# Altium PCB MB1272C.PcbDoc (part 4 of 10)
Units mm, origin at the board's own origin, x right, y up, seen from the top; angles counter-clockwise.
Board outline 101 x 71 mm, 6 copper layers (Top Layer, Signal Layer 1, Signal Layer 2, Signal Layer 3, Signal Layer 4, Bottom Layer), stack 1.552 mm thick; 520 components, 478 nets, 2156 pads, 1894 vias.
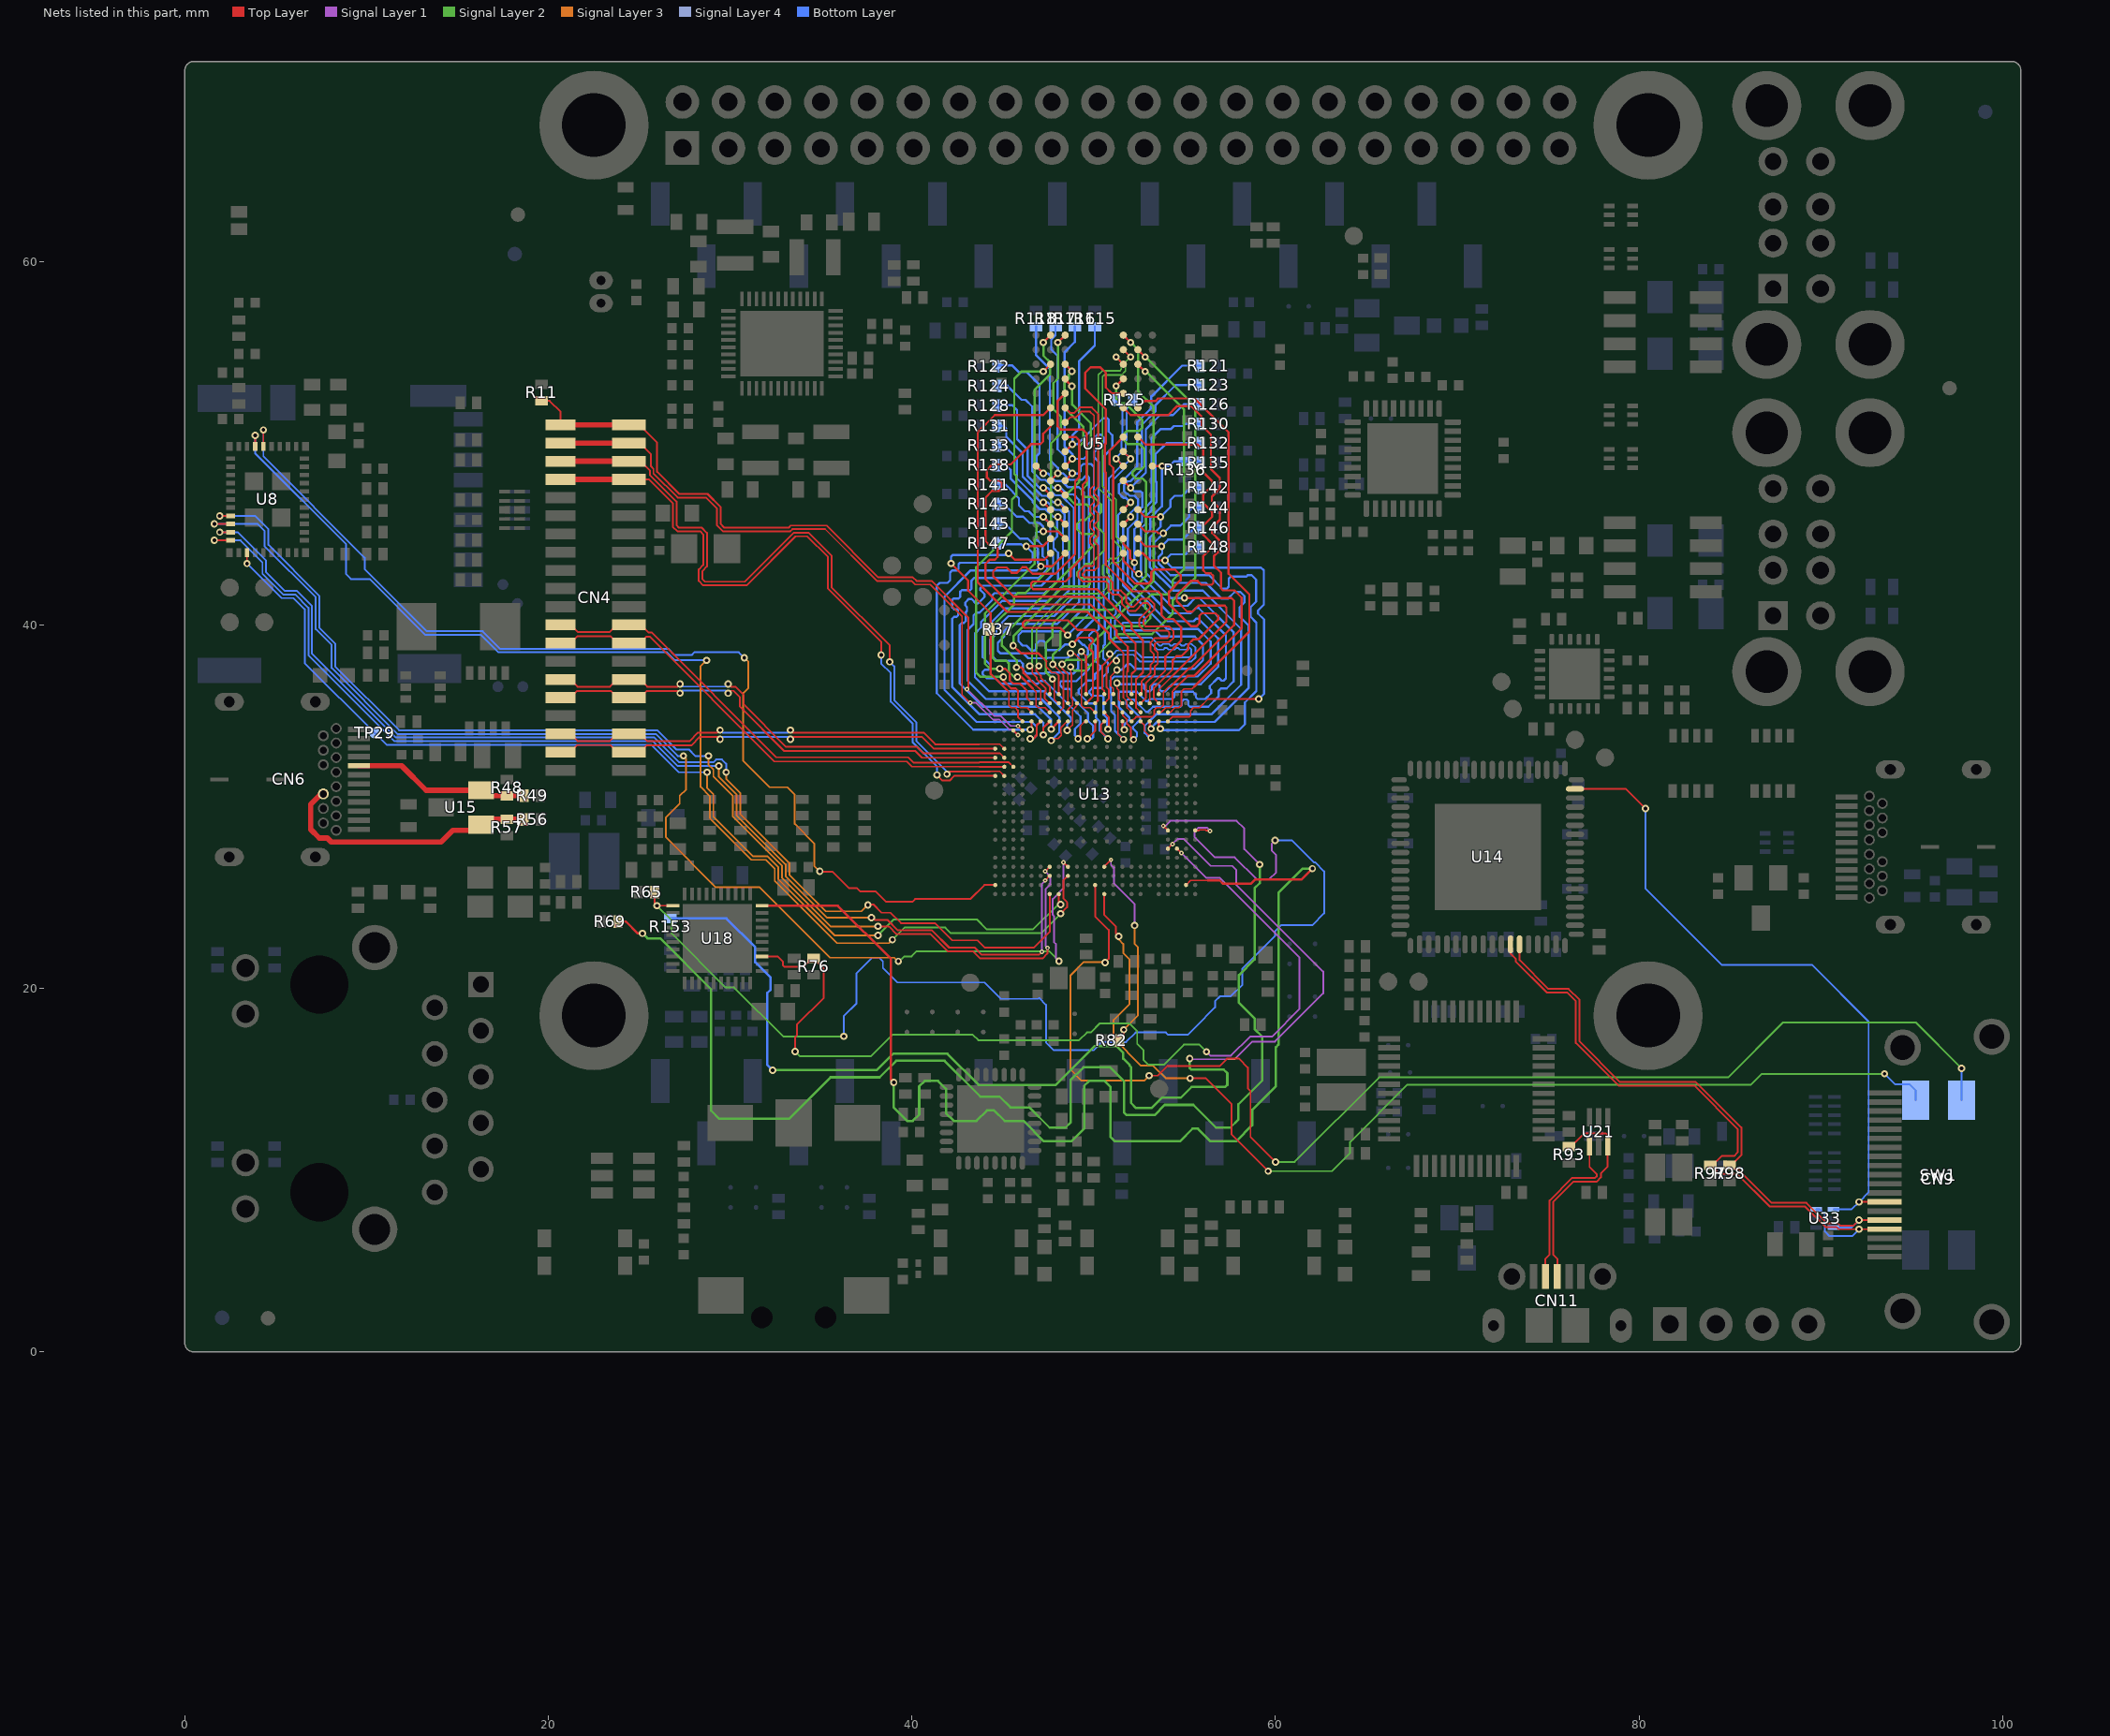
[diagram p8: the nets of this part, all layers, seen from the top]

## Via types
v1: diameter 0.4, hole 0.2, Top Layer to Bottom Layer, tented both sides, 912 vias
v2: diameter 0.25, hole 0.1, Top Layer to Signal Layer 1, tented top, 493 vias
v3: diameter 0.6, hole 0.3, Top Layer to Bottom Layer, tented both sides, 452 vias
v4: diameter 0.25, hole 0.1, Top Layer to Signal Layer 1, tented both sides, 37 vias

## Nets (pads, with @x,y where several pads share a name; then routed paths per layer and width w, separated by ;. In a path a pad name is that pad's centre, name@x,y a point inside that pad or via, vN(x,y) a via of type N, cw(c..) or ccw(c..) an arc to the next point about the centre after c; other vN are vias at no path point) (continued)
BOOT0: SW1.1 U13.N1 | length 60.5
  Top Layer w0.1: U13.N1@50.58,25.19 50.58,24.034 51.23,23.384 51.23,23.015 v1(51.38,22.865) ; v1(55.3,15.05) 56.175,15.05 57.575,13.65 57.575,11.97 v1(59.6,9.945)
  Signal Layer 2 w0.1: v1(59.6,9.945) 63.095,9.945 64.1,10.95 64.1,11.55 67.25,14.7 86.15,14.7 86.75,15.3 v1(93.5,15.3)
  Signal Layer 3 w0.1: v1(51.38,22.865) 51.38,22.694 51.625,22.449 51.625,21.95 51.975,21.6 51.975,19.15 51.1,18.275 51.1,17.25 52.6,15.75 53.278,15.75 53.978,15.05 v1(55.3,15.05)
  Bottom Layer w0.1: v1(93.5,15.3) 94.075,14.725 94.875,14.725 95.205,14.395 SW1.1@95.205,13.85
BOOT1: R82.2 U13.N4 | length 11.5
  Top Layer w0.1: U13.N4@50.575,26.695 U13.N4@50.58,26.69 50.58,26.705 v2(50.95,27.075) ; R82.2@51.425,17.125 51.65,17.35 v1(51.65,17.725)
  Signal Layer 1 w0.1: v2(50.95,27.075) 50.95,26.8 51.105,26.645 51.105,25.787 52.255,24.636 v1(52.255,23.465)
  Signal Layer 3 w0.1: v1(51.65,17.725) 52.425,18.5 52.425,22.275 52.255,22.445 v1(52.255,23.465)
BOOT2: SW1.2 U13.M2 | length 72.3
  Top Layer w0.1: U13.M2@50.08,25.69 50.08,23.968 50.83,23.218 50.83,21.63 v1(50.625,21.425) ; v1(53.05,15.2) 53.525,15.2 54.05,15.725 56.926,15.725 57.331,16.129 57.996,16.129 58.475,15.65 58.475,14.495 58.625,14.345 58.625,11.825 v1(60,10.45)
  Signal Layer 2 w0.1: v1(60,10.45) 61.05,10.45 65.7,15.1 84.9,15.1 87.925,18.125 95.215,18.125 v1(97.745,15.595)
  Signal Layer 3 w0.1: v1(50.625,21.425) 50.625,21.45 49.45,21.45 48.725,20.725 48.725,15.525 49.325,14.925 52.775,14.925 v1(53.05,15.2)
  Bottom Layer w0.1: SW1.2@97.745,13.85 v1(97.745,15.595)
BT_DEV_WAKE: U8.39 U13.J3 | length 67
  Top Layer w0.09: 48.53,24.715 48.53,24.753 48.33,24.953 48.33,25.94 U13.J3@48.58,26.19
  Top Layer w0.1: U8.39@3.875,49.825 v1(3.875,50.425) ; v1(48.18,24.115) 48.53,24.465 48.53,24.715
  Signal Layer 2 w0.1: v1(38.925,22.675) 39.6,23.35 41.84,23.35 42.15,23.04 47.105,23.04 v1(48.18,24.115)
  Signal Layer 3 w0.1: v1(28.7,38.05) 28.38,37.73 28.38,31.09 28.88,30.59 28.88,29.356 31.161,27.075 31.953,27.075 32.455,26.573 32.455,25.917 35.882,22.49 38.74,22.49 v1(38.925,22.675)
  Bottom Layer w0.1: v1(3.875,50.425) 3.875,49.44 8.875,44.44 8.875,42.789 9.139,42.525 10.167,42.525 13.242,39.45 16.3,39.45 17.26,38.49 26.519,38.49 26.959,38.05 v1(28.7,38.05)
BT_HOST_WAKE: U8.38 U13.A2 | length 58.9
  Top Layer w0.1: U8.38@4.325,49.825 v1(4.325,50.726) ; v1(34.93,26.44) 34.955,26.415 35.644,26.415 36.554,25.506 36.98,25.506 37.144,25.341 38.004,25.341 38.58,24.765 40.03,24.765 40.18,24.915 43.208,24.915 43.983,25.69 U13.A2@44.58,25.69
  Signal Layer 3 w0.1: v1(30.78,38.19) 31.004,37.966 31.004,36.531 30.725,36.252 30.725,32.509 32.168,31.066 33.148,31.066 33.55,30.664 33.55,29.049 34.63,27.969 34.63,26.74 v1(34.93,26.44)
  Bottom Layer w0.1: v1(4.325,50.726) 4.325,49.272 9.901,43.697 9.901,43.074 13.325,39.65 16.383,39.65 17.343,38.69 26.601,38.69 26.951,38.34 27.882,38.34 28.032,38.49 30.48,38.49 v1(30.78,38.19)
BT_PCM_CLK: U8.11 U13.G3 | length 63.7
  Top Layer w0.1: v1(1.624,44.65) U8.11@2.525,44.65 ; v1(37.78,23.89) v1@37.78,23.94 ; v1@37.78,23.94 37.955,23.765 38.661,23.765 39.237,23.19 41.104,23.19 42.049,22.245 43.442,22.245 43.837,21.85 46.99,21.85 v4(47.15,22.01) ; v2(47.33,25.94) U13.G3@47.58,26.19
  Signal Layer 1 w0.1: v4(47.15,22.01) 47.15,25.76 v2(47.33,25.94)
  Signal Layer 3 w0.1: v1(29.38,32.24) 29.38,31.639 30.35,30.669 30.35,29.526 33.055,26.821 33.055,26.165 35.33,23.89 v1(37.78,23.89)
  Bottom Layer w0.1: v1(1.624,44.65) 3.067,44.65 4.275,43.442 4.275,42.806 5.406,41.675 6.069,41.675 6.8,40.944 6.8,38.336 11.536,33.6 25.745,33.6 27.105,32.24 28.805,32.24 v1(29.38,32.24)
BT_PCM_SDI: U8.10 U13.G1 | length 62
  Top Layer w0.1: v1(1.925,45.1) U8.10@2.525,45.1 ; v1(37.58,24.59) 37.605,24.615 37.882,24.615 38.332,24.165 38.827,24.165 39.402,23.59 41.269,23.59 42.214,22.645 43.608,22.645 44.003,22.25 46.713,22.25 47.58,23.117 U13.G1@47.58,25.19
  Signal Layer 3 w0.1: v1(29.78,31.89) 29.78,31.522 30.55,30.752 30.55,29.609 33.255,26.904 33.255,26.248 35.263,24.24 37.225,24.24 37.575,24.59 v1(37.58,24.59)
  Bottom Layer w0.1: v1(1.925,45.1) 2.9,45.1 4.475,43.525 4.475,42.889 5.489,41.875 6.152,41.875 7,41.027 7,38.419 11.619,33.8 25.828,33.8 27.188,32.44 29.08,32.44 29.23,32.59 29.555,32.59 29.78,32.365 v1(29.78,31.89)
BT_PCM_SDO: U8.9 U13.J4 | length 70.5
  Top Layer w0.1: v1(1.624,45.55) U8.9@2.525,45.55 ; v2(48.33,26.94) U13.J4@48.58,26.69
  Signal Layer 1 w0.1: v1(48.09,21.5) 47.92,21.67 47.92,21.867 47.925,21.872 47.925,22.427 47.816,22.536 47.816,23.984 47.75,24.05 47.75,24.92 48.33,25.5 v2(48.33,26.94)
  Signal Layer 2 w0.1: v1(39.255,21.49) 39.255,21.44 39.579,21.765 39.98,21.765 40.255,22.04 47.55,22.04 v1(48.09,21.5)
  Signal Layer 3 w0.1: v1(27.429,32.79) 27.58,32.64 27.58,30.949 27.225,30.594 27.225,30.16 26.475,29.41 26.475,28.311 29.221,25.565 31.624,25.565 35.499,21.69 39.03,21.69 39.23,21.49 v1(39.255,21.49)
  Signal Layer 4 w0.1: v1(27.429,32.79) v1@27.48,32.74
  Bottom Layer w0.1: v1(1.624,45.55) 4.017,45.55 4.4,45.167 4.4,44.317 7.2,41.517 7.2,39.761 8.075,38.886 8.075,38.513 ; 8.074,38.512 8.074,37.628 11.702,34 25.911,34 27.12,32.79 v1(27.429,32.79)
BT_PCM_WS: U8.8 U13.G4 | length 65.3
  Top Layer w0.1: v1(1.925,46) U8.8@2.525,46 ; v1(38.13,23.415) 38.729,23.414 39.154,22.99 41.021,22.99 41.966,22.045 43.359,22.045 43.754,21.65 47.179,21.65 47.45,21.921 v4(47.45,22.23) ; v2(47.33,26.44) U13.G4@47.58,26.69
  Signal Layer 1 w0.1: v2(47.33,26.44) 47.605,26.165 47.605,25.715 47.35,25.46 47.35,22.33 v4(47.45,22.23)
  Signal Layer 3 w0.1: v1(28.805,32.79) 28.805,32.315 29.08,32.04 29.08,31.656 30.15,30.586 30.15,29.444 32.855,26.739 32.855,26.082 35.522,23.415 v1(38.13,23.415)
  Bottom Layer w0.1: v1(1.925,46) 3.85,46 4.6,45.25 4.6,44.4 7.4,41.6 7.4,39.844 8.275,38.969 8.275,37.886 8.274,37.711 11.785,34.2 25.994,34.2 27.053,33.14 27.73,33.14 28.08,32.79 v1(28.805,32.79)
BT_REG_ON: TP29.1 U8.14 U13.H1 | length 59.1
  Top Layer w0.1: v1(3.425,43.375) U8.14@3.425,43.975 ; U13.H1@48.08,25.19 48.08,24.64 48.105,24.615 v1(48.18,24.615)
  Signal Layer 2 w0.1: v1(38.13,22.915) 39.005,23.79 43.58,23.79 44.13,23.24 44.81,23.24 46.655,23.24 48.105,24.69 v1(48.18,24.615)
  Signal Layer 3 w0.1: v1(28.73,31.89) 28.73,31.04 29.08,30.69 29.08,29.439 31.244,27.275 32.036,27.275 32.655,26.656 32.655,25.999 35.74,22.915 v1(38.13,22.915)
  Bottom Layer w0.1: v1(3.425,43.375) 3.425,43.373 5.323,41.475 5.986,41.475 6.6,40.861 6.6,37.9 TP29.1@10.45,34.05 11.1,33.4 25.662,33.4 27.172,31.89 v1(28.73,31.89)
CC1: CN6.A5 R48.2 R49.1 U15.2 | length 9.8
  Top Layer w0.3: CN6.A5@9.58,32.25 11.925,32.25 13.275,30.9 U15.2@16.3,30.9 16.6,30.6 R48.2@17.725,30.6 R49.1@18.65,30.6
CC2: CN6.B5 R56.1 R57.2 U15.1 | length 14.8
  Top Layer w0.3: CN6.B5@7.62,30.7 7.501,30.7 6.925,30.124 6.925,28.75 7.4,28.275 7.5,28.275 7.505,28.28 7.83,28.28 8.061,28.05 14.1,28.05 14.75,28.7 16,28.7 U15.1@16.3,29 16.6,29.3 R57.2@17.725,29.3 R56.1@18.65,29.3
CEC_A: CN9.13 U14.71 U33.1 | length 37.1
  Top Layer w0.1: U14.71@76.475,30.975 79.275,30.975 v1(80.35,29.9) ; v1(92.1,8.25) CN9.13@93.5,8.25
  Bottom Layer w0.1: v1(80.35,29.9) 80.35,25.5 84.55,21.3 89.5,21.3 92.625,18.175 92.625,8.775 v1(92.1,8.25) 91.7,7.85 U33.1@90.7,7.85
CON_USB_STLK_N: CN11.2 U21.1 | length 9.2
  Top Layer w0.1: CN11.2@74.85,4.15 74.85,5.125 75.075,5.35 75.075,8.325 76.325,9.575 77.575,9.575 77.675,9.675 77.675,9.775 77.275,10.175 U21.1@77.275,11.295
CON_USB_STLK_P: CN11.3 R93.1 U21.3 | length 12.3
  Top Layer w0.1: CN11.3@75.5,4.15 75.5,5.125 75.275,5.35 75.275,8.242 76.408,9.375 77.675,9.375 77.9,9.6 77.9,9.825 78.275,10.2 U21.3@78.275,11.295 78.275,11.925 78.175,12.025 77,12.025 76.275,11.3 R93.1@76.15,11.3
DDR_A0: R131.1 U5.N3 U13.L20 | length 29.5
  Top Layer w0.09: v1(48.03,46.74) U5.N3@48.43,46.34 ; v1(49.14,33.74) 49.26,33.86 49.26,34.43 49.52,34.69 U13.L20@49.58,34.69
  Bottom Layer w0.12: R131.1@44.68,50.96 45.03,50.96 45.19,50.8 45.19,50.34 46.09,49.44 46.09,48.16 47.15,47.1 47.42,47.1 47.78,46.74 v1(48.03,46.74) 48.121,46.74 48.64,46.221 48.64,41.895 47.645,40.9 45.132,40.9 44.23,39.998 44.23,39.698 43.89,39.358 43.89,38.226 44.323,37.793 44.323,37.647 44.206,37.53 44.01,37.53 43.89,37.41 43.89,37.292 44.106,37.076 44.563,37.076 44.879,36.76 46.24,36.76 46.39,36.91 46.635,36.91 46.785,36.76 46.92,36.76 47.07,36.91 47.319,36.91 49.27,34.959 49.27,34.58 48.96,34.27 48.96,33.92 v1(49.14,33.74)
DDR_A1: R123.1 U5.P7 U13.P22 | length 34
  Top Layer w0.09: U13.P22@51.08,35.69 51.335,35.435 ; 51.33,34.005 51.33,35.435 ; 51.335,34.005 v1(51.64,33.7)
  Top Layer w0.12: U5.P7@51.63,45.54 v1(52.03,45.94)
  Bottom Layer w0.12: v1(51.64,33.7) 51.17,34.17 51.17,35.032 50.96,35.242 50.96,36.26 50.92,36.3 50.92,36.949 51.131,37.16 55.719,37.16 56.43,37.871 56.43,39.079 55.729,39.78 54.01,39.78 51.61,42.18 51.61,45.52 v1(52.03,45.94) 52.03,46.162 52.447,46.579 52.447,46.903 52.25,47.1 51.981,47.1 51.861,47.22 51.81,47.22 51.665,47.365 51.665,47.684 51.881,47.9 52.01,47.9 52.65,48.54 52.65,51 53.39,51.74 53.39,52.079 54.501,53.19 R123.1@55.86,53.19
DDR_A2: R138.1 U5.P3 U13.J20 | length 27.4
  Top Layer w0.09: v1@47.76,33.74 48.04,33.74 48.22,33.92 48.22,34.032 48.195,34.057 48.195,34.343 48.542,34.69 U13.J20@48.58,34.69
  Top Layer w0.12: v1(47.66,33.64) v1@47.76,33.74 ; v1(48.03,45.94) U5.P3@48.43,45.54
  Bottom Layer w0.12: R138.1@44.68,48.79 45.17,48.79 45.43,48.53 45.43,48.049 46.64,46.839 46.64,46.76 47.04,46.36 47.36,46.36 47.78,45.94 v1(48.03,45.94) ; v1(47.66,33.64) 48.12,34.1 48.12,34.921 47.121,35.92 44.074,35.92 43.05,36.944 43.05,39.706 43.39,40.046 43.39,40.522 43.548,40.68 43.72,40.68 43.722,40.678 44.42,41.376 44.42,41.62 44.54,41.74 47.297,41.74 48.037,42.48 48.037,43.973 47.79,44.22 47.79,44.66 47.987,44.857 v1@47.987,45.92
DDR_A3: R133.1 U5.N2 U13.K22 | length 27.8
  Top Layer w0.09: v1(48.54,34.2) 48.825,34.485 ; 48.83,34.485 48.83,35.3 49.08,35.575 U13.K22@49.08,35.69 U13.K22@49.08,35.58
  Top Layer w0.12: v1(47.23,46.74) U5.N2@47.63,46.34
  Bottom Layer w0.12: R133.1@44.68,49.88 45.05,49.88 45.77,49.16 45.77,48.07 47.1,46.74 v1(47.23,46.74) 47.469,46.74 47.879,46.33 48.149,46.33 48.39,46.089 48.39,45.791 48.307,45.708 48.307,42.156 47.471,41.32 44.958,41.32 43.81,40.172 43.81,39.872 43.47,39.532 43.47,37.118 44.248,36.34 47.295,36.34 48.75,34.885 48.75,34.73 48.54,34.52 v1(48.54,34.2)
DDR_A4: R144.1 U5.P8 U13.V20 | length 24.5
  Top Layer w0.12: U5.P8@52.43,45.54 52.83,45.14 53.45,45.14 53.55,45.04 v1(53.83,45.04) ; U13.V20@53.08,34.69 53.08,34.37 v1(53.16,34.29)
  Bottom Layer w0.12: v1(53.16,34.29) 53.16,34.334 53.486,34.66 56.654,34.66 58.53,36.536 58.53,39.949 58.03,40.449 58.03,40.968 58.291,41.229 58.291,41.589 58.075,41.805 57.745,41.805 57.38,41.44 57.039,41.44 56.166,42.313 54.3,42.313 53.32,43.292 53.32,44.51 53.85,45.04 v1(53.83,45.04) 54.25,45.46 54.76,45.46 55.25,45.95 55.25,46.24 55.45,46.44 R144.1@55.86,46.44
DDR_A5: R141.1 U5.P2 U13.H20 | length 25.6
  Top Layer w0.12: v1(47.23,45.94) U5.P2@47.63,45.54 ; v1(47.66,34.26) 48.08,34.68 U13.H20@48.08,34.69
  Bottom Layer w0.12: R141.1@44.68,47.71 45.17,47.71 45.555,47.325 45.555,47.295 45.89,46.96 45.89,46.57 46.205,46.255 46.425,46.255 46.74,45.94 v1(47.23,45.94) 47.612,45.558 47.612,44.942 47.487,44.817 47.487,44.11 47.767,43.829 47.767,42.804 47.123,42.16 43.91,42.16 43.77,42.02 43.77,41.91 44,41.68 44,41.55 43.63,41.18 43.52,41.18 43.27,41.43 43.138,41.43 42.94,41.232 42.94,41.07 43.032,40.978 43.032,40.758 42.97,40.696 42.97,40.22 42.86,40.11 42.75,40.11 42.63,39.99 42.63,36.77 43.9,35.5 46.947,35.5 47.66,34.787 v1(47.66,34.26) v1@47.67,34.25
DDR_A6: R146.1 U5.R8 U13.W20 | length 25.3
  Top Layer w0.12: U5.R8@52.38,44.727 U5.R8@52.38,44.74 ; U5.R8@52.43,44.74 52.85,44.32 v1(53.73,44.32) ; v1@53.58,34.37 U13.W20@53.58,34.69
  Bottom Layer w0.12: v1@53.66,34.24 53.69,34.21 57.99,34.21 58.314,34.534 58.314,35.726 58.95,36.362 58.95,40.123 58.62,40.453 58.62,40.964 58.935,41.279 58.935,42.485 58.687,42.733 58.47,42.733 58.402,42.665 57.545,42.665 57.43,42.55 57.43,42.1 57.32,41.99 57.083,41.99 56.34,42.733 54.219,42.733 53.56,43.392 53.56,43.734 53.766,43.94 v1@53.766,44.315 ; v1(53.73,44.32) 54.095,44.685 54.88,44.685 55.545,45.35 R146.1@55.86,45.35
  other v1: 53.66,34.29
DDR_A7: R147.1 U5.R2 U13.E20 | length 22.7
  Top Layer w0.12: v1(46.29,44.32) 46.311,44.34 47.23,44.34 U5.R2@47.63,44.74 ; v1(46.51,34.24) 46.58,34.31 U13.E20@46.58,34.69
  Bottom Layer w0.12: R147.1@44.68,44.49 44.73,44.44 46.02,44.44 46.14,44.32 v1(46.29,44.32) 46.65,43.96 46.65,43.59 46.48,43.42 42.64,43.42 42.56,43.34 42.56,43.08 42.47,42.99 42.21,42.99 42.1,42.88 42.1,42.454 41.956,42.31 41.53,42.31 41.37,42.15 41.37,36.248 43.378,34.24 v1(46.51,34.24)
DDR_A8: R148.1 U5.T8 U13.Y20 | length 22.7
  Top Layer w0.09: U13.Y20@54.08,34.69 54.33,34.94 55.265,34.94 55.325,35 55.325,35.275 55.49,35.44 55.815,35.44 56.295,35.92 v1(59.08,35.92)
  Top Layer w0.12: U5.T8@52.43,43.94 52.706,43.94 53.096,43.55 v1(53.92,43.55)
  Bottom Layer w0.09: 59.35,41.1 59.355,41.1
  Bottom Layer w0.12: R148.1@55.86,44.27 55.45,44.27 55.06,43.88 54.25,43.88 v1(53.92,43.55) 54.317,43.153 59.207,43.153 59.355,43.005 59.355,41.1 ; v1(59.08,35.92) 59.37,36.21 59.37,40.297 59.04,40.627 59.04,40.79 59.35,41.1
DDR_A9: R143.1 U5.R3 U13.G20 | length 26.4
  Top Layer w0.12: v1(47.23,33.95) 47.23,34.34 U13.G20@47.58,34.69 ; v1(47.23,45.14) 48.03,45.14 U5.R3@48.43,44.74
  Bottom Layer w0.12: R143.1@44.68,46.65 45.07,46.65 45.76,45.96 46.12,45.96 46.469,45.61 47.02,45.61 47.23,45.4 v1(47.23,45.14) ; v1@47.187,45.12 46.88,45.12 46.81,45.05 46.81,44.74 47.187,44.363 47.187,43.795 47.45,43.532 47.45,43.071 46.959,42.58 43.42,42.58 43.28,42.44 43.28,41.99 43.21,41.92 42.754,41.92 42.662,41.828 42.662,41.548 42.564,41.45 42.284,41.45 42.21,41.376 42.21,40.97 42.32,40.86 42.5,40.86 42.54,40.82 42.54,40.52 42.46,40.44 42.32,40.44 42.21,40.33 42.21,36.596 43.726,35.08 46.773,35.08 47.23,34.623 ; v1(47.23,33.95) 47.23,34.623 ; 47.24,34.613 47.23,34.623
DDR_A10: R126.1 U5.L7 U13.R22 | length 29.7
  Top Layer w0.09: v1(51.28,36.8) 51.28,36.5 51.37,36.41 51.37,35.9 U13.R22@51.58,35.69
  Top Layer w0.12: U5.L7@51.63,47.94 v1(52.03,47.54)
  Bottom Layer w0.12: v1@51.34,36.74 52.71,36.74 52.77,36.68 52.77,36.51 52.94,36.34 53.08,36.34 53.21,36.47 53.21,36.65 53.3,36.74 53.54,36.74 53.63,36.65 53.63,36.44 53.73,36.34 53.93,36.34 54.33,36.74 55.893,36.74 56.85,37.697 56.85,39.253 55.769,40.334 55.626,40.334 55.492,40.2 54.04,40.2 51.88,42.36 51.88,45.281 52.4,45.801 52.4,46.22 52.647,46.468 ; 52.667,46.468 52.667,47.263 52.58,47.35 52.22,47.35 v1(52.03,47.54) 52.87,48.38 52.87,50.759 53.651,51.54 54.361,51.54 54.961,52.14 55.85,52.14 R126.1@55.86,52.13
DDR_A11: R130.1 U5.R7 U13.R20 | length 32.2
  Top Layer w0.09: U13.R20@51.58,34.69 51.58,34.33 v1(51.68,34.23)
  Top Layer w0.12: U5.R7@51.63,44.74 51.63,44.449 52.01,44.069 52.01,43.66 v1(52.24,43.43)
  Bottom Layer w0.12: v1(51.68,34.23) 51.68,34.507 51.97,34.797 51.97,34.897 51.74,35.127 51.733,35.127 51.381,35.479 51.381,36.241 51.46,36.32 52.366,36.32 52.878,35.808 52.981,35.808 53.093,35.92 54.32,35.92 54.43,36.03 54.43,36.24 54.51,36.32 55.46,36.32 55.628,36.152 55.628,36.01 55.718,35.92 56.132,35.92 56.461,36.249 56.461,36.429 56.38,36.51 56.38,36.633 56.808,37.062 56.908,37.062 57.046,36.924 57.136,36.924 57.27,37.058 57.27,39.427 55.768,40.929 55.626,40.929 55.331,40.633 54.148,40.633 52.12,42.661 52.12,42.959 52.24,43.079 v1(52.24,43.43) 52.24,45.261 52.66,45.68 52.66,46.149 52.887,46.377 52.887,46.496 53.18,46.789 53.18,50.269 53.691,50.78 54.26,50.78 54.42,50.94 54.899,50.94 55.019,51.06 R130.1@55.86,51.06
DDR_A12: R121.1 U5.N7 U13.P23 | length 33
  Top Layer w0.09: U13.P23@51.08,36.19 51.08,36.5 50.935,36.645 50.935,37.175 v1(51.28,37.52)
  Top Layer w0.12: U5.N7@51.63,46.34 v1(52.03,46.74)
  Bottom Layer w0.12: v1(51.28,37.52) 51.53,37.52 51.86,37.85 52,37.85 52.27,37.58 55.545,37.58 56.01,38.045 56.01,38.905 55.555,39.36 53.692,39.36 53.352,39.7 51.65,39.7 51.57,39.78 51.57,40.06 51.63,40.12 52.726,40.12 52.838,40.232 52.838,40.358 52.656,40.54 52.002,40.54 51.862,40.68 51.862,40.912 52.07,41.12 52.07,41.32 51.9,41.49 51.562,41.49 51.34,41.712 51.34,46.05 v1(52.03,46.74) 51.79,46.98 51.65,46.98 51.39,47.24 51.39,47.725 52.397,48.732 52.397,51.157 53.17,51.93 53.17,52.57 54.86,54.26 R121.1@55.86,54.26
DDR_A13: R145.1 U5.T3 U13.F20 | length 24.7
  Top Layer w0.12: v1(46.51,33.74) 46.67,33.74 46.87,33.94 46.87,34.48 U13.F20@47.08,34.69 ; v1@47.12,43.23 47.72,43.23 U5.T3@48.43,43.94
  Bottom Layer w0.12: R145.1@44.68,45.57 45.12,45.57 45.945,44.745 46.374,44.745 46.93,44.189 46.93,43.39 47.09,43.23 46.86,43 43.24,43 41.79,41.55 41.79,36.422 43.552,34.66 46.39,34.66 46.599,34.66 46.87,34.389 46.87,33.94 46.67,33.74 v1(46.51,33.74) ; v1@47.12,43.18 v1@47.12,43.23
  other v1: 47.09,43.22
DDR_A14: R132.1 U5.T7 U13.R21 | length 33.2
  Top Layer w0.09: U13.R21@51.557,35.167 U13.R21@51.58,35.19 ; U13.R21@51.583,35.21 51.587,35.206 51.587,35.036 51.684,34.94 51.83,34.794 51.83,34.586 51.83,34.568 52.04,34.358 52.04,33.84 v1(52.19,33.69)
  Top Layer w0.12: U5.T7@51.63,43.94 51.63,43.52 52.34,42.81 v1(52.48,42.81)
  Bottom Layer w0.12: v1@52.17,33.66 52.38,33.87 52.38,34.08 52.158,34.302 52.158,34.392 52.558,34.792 52.558,34.903 51.801,35.66 51.801,35.83 51.871,35.9 52.192,35.9 52.881,35.211 ; 52.88,35.21 52.977,35.21 53.267,35.5 54.77,35.5 54.85,35.58 54.85,35.79 54.96,35.9 55.11,35.9 55.208,35.802 55.208,35.58 55.288,35.5 56.306,35.5 56.881,36.075 56.881,36.39 56.995,36.504 57.31,36.504 57.69,36.884 57.69,39.601 55.818,41.473 55.577,41.473 55.157,41.053 54.242,41.053 52.825,42.47 52.82,42.47 v1(52.48,42.81) 52.6,42.93 52.6,45.309 52.88,45.589 52.88,46 53.19,46.311 53.19,46.488 53.44,46.738 53.44,47.869 53.4,47.909 53.4,49.389 54.02,50.009 55.841,50.009 R132.1@55.86,49.99
DDR_BA0: R128.1 U5.M2 U13.L23 | length 29.4
  Top Layer w0.12: v1(47.23,47.54) U5.M2@47.63,47.14 ; v1(49.32,38.54) 49.58,38.28 U13.L23@49.58,36.19
  Bottom Layer w0.12: R128.1@44.68,52.06 44.71,52.09 45.51,52.09 45.78,51.82 45.78,50.22 46.37,49.63 46.37,48.191 47.021,47.54 v1(47.23,47.54) 47.469,47.54 47.879,47.13 48.2,47.13 48.91,46.42 48.91,41.571 47.819,40.48 45.306,40.48 44.65,39.824 44.65,39.524 44.31,39.184 44.31,38.4 44.69,38.02 45.949,38.02 46.11,37.859 46.11,37.56 46.34,37.33 47.3,37.33 47.35,37.38 48.531,37.38 48.59,37.32 48.87,37.32 49.14,37.591 49.14,38.36 v1(49.32,38.54)
DDR_BA1: R142.1 U5.N8 U13.U20 | length 25.3
  Top Layer w0.09: U13.U20@52.58,34.69 52.78,34.49 52.78,34.17 v1(53.16,33.79)
  Top Layer w0.12: U5.N8@52.43,46.34 52.83,45.94 v1(53.68,45.94)
  Bottom Layer w0.12: v1(53.16,33.79) 53.066,33.79 52.8,34.056 52.8,34.439 53.441,35.08 56.48,35.08 58.11,36.71 58.11,39.775 55.992,41.893 54.38,41.893 53.08,43.193 53.08,44.799 53.68,45.399 v1(53.68,45.94) 54.22,46.48 54.22,46.869 54.451,47.1 54.88,47.1 55.34,47.56 55.84,47.56 R142.1@55.86,47.54
DDR_BA2: R124.1 U5.M3 U13.M21 | length 29.9
  Top Layer w0.09: v1(48.72,38.44) 48.929,38.44 49.335,38.034 ; 49.33,38.034 49.33,35.559 49.449,35.44 49.82,35.44 50.07,35.19 U13.M21@50.08,35.19
  Top Layer w0.12: v1@48.05,47.52 U5.M3@48.43,47.14
  Bottom Layer w0.12: R124.1@44.68,53.15 44.71,53.18 45.25,53.18 45.25,53.161 46.031,52.38 46.249,52.38 46.62,52.009 46.62,48.441 47.081,47.98 47.34,47.98 47.78,47.54 v1(48.03,47.54) 48.19,47.54 48.554,47.176 48.894,47.176 49.2,46.87 49.2,41.267 47.993,40.06 45.48,40.06 45.07,39.65 45.07,39.35 44.73,39.01 44.73,38.574 44.864,38.44 46.123,38.44 46.401,38.162 47.432,38.162 47.46,38.19 48.57,38.19 v1@48.72,38.34 ; v1@48.64,38.32 v1@48.72,38.4
DDR_CASN: R116.1 U5.K3 U13.N20 | length 31.1
  Top Layer w0.09: U13.N20@50.58,34.69 50.39,34.5 50.39,34.13 v1(50.78,33.74)
  Top Layer w0.12: U5.K3@48.43,48.74 v1(48.83,49.14)
  Bottom Layer w0.12: R116.1@48.97,56.41 48.97,55.57 48.39,54.99 48.39,49.83 48.83,49.39 v1(48.83,49.14) 49.45,49.14 49.61,49.3 49.61,49.866 50.202,50.458 50.409,50.458 50.58,50.287 50.58,50.07 50.03,49.52 50.03,49.212 50.28,48.962 50.28,39.77 50.17,39.66 ; 50.169,39.661 49.969,39.661 49.75,39.441 49.75,39.203 50.1,38.853 50.1,37.996 50.36,37.736 50.36,37.577 50.08,37.297 50.08,37.05 49.97,36.94 49.677,36.94 49.168,36.431 49.168,36.248 49.736,35.681 50,35.681 50.12,35.561 50.12,34.894 50.33,34.684 50.33,34.19 v1(50.78,33.74)
DDR_CKE: R135.1 R136.2 U5.K9 U13.T20 | length 24.3
  Top Layer w0.09: U13.T20@52.08,34.69 52.33,34.94 53.205,34.94 53.33,35.065 53.33,35.324 53.446,35.44 53.694,35.44 53.83,35.576 53.83,36.303 54.147,36.62 54.25,36.62
  Top Layer w0.12: U5.K9@53.23,48.74 v1(53.76,48.74) ; 54.25,36.62 55.24,37.61 55.344,37.61 57.72,39.986 57.72,41.33 57.57,41.48 v1(54.99,41.48)
  Bottom Layer w0.12: 53.12,45.23 53.12,45.24 ; v1(54.99,41.48) 54.25,41.48 52.84,42.89 52.84,44.96 53.12,45.24 ; R135.1@55.86,48.91 55.78,48.99 R136.2@55.01,48.99 55,49 54.41,49 54.15,48.74 v1(53.76,48.74) 53.76,46.53 53.12,45.89 53.12,45.24
DDR_CLK_N: R125.2 U5.K7 U13.N23 | length 27
  Top Layer w0.1: U13.N23@50.58,36.19 50.58,36.371 50.49,36.461 50.49,36.465 50.48,36.475 50.48,37.77 50.88,38.17 v1(50.88,38.39) ; v1(51.23,49.14) U5.K7@51.63,48.74
  Bottom Layer w0.1: v1(50.88,38.39) 50.91,38.42 51.1,38.42 51.267,38.587 52.268,38.587 52.635,38.22 55.28,38.22 55.37,38.31 55.37,38.64 55.29,38.72 55.165,38.72 55.085,38.64 54.73,38.64 54.65,38.72 54.525,38.72 54.445,38.64 54.12,38.64 54.04,38.72 53.905,38.72 53.825,38.64 53.507,38.64 53.087,39.06 51.185,39.06 50.93,39.315 50.93,40.325 51.222,40.617 51.222,40.919 50.835,41.306 50.835,48.075 51.513,48.753 51.513,48.867 v1@51.24,49.14 ; v1(51.23,49.14) 51.23,49.19 51.52,49.48 51.52,50.21 51.58,50.27 51.58,51.89 51.24,52.23 R125.2@51.24,52.36
DDR_CLK_P: R125.1 U5.J7 U13.N22 | length 27.5
  Top Layer w0.09: 50.83,35.94 50.83,36.446
  Top Layer w0.1: U13.N22@50.58,35.69 50.83,35.94 ; 50.83,36.446 50.72,36.556 50.72,36.56 50.71,36.57 50.71,37.675 51.075,38.04 v1(51.25,38.04) ; U5.J7@51.63,49.54 v1(52.03,49.14)
  Bottom Layer w0.1: 51.065,41.401 51.069,41.401 51.069,47.984 51.743,48.657 51.743,48.85 52.03,49.137 v1(52.03,49.14) 51.75,49.42 51.75,50.114 51.81,50.174 51.81,51.89 52.14,52.22 R125.1@52.14,52.36 ; 51.11,41.36 51.452,41.018 51.452,40.522 51.16,40.23 51.16,39.41 51.28,39.29 53.182,39.29 53.602,38.87 53.73,38.87 53.81,38.95 54.135,38.95 54.215,38.87 54.35,38.87 54.43,38.95 54.745,38.95 54.825,38.87 54.99,38.87 55.07,38.95 55.385,38.95 55.6,38.735 55.6,38.215 55.375,37.99 52.54,37.99 52.173,38.357 51.363,38.357 51.26,38.255 51.26,38.05 v1(51.25,38.04)
DDR_CSN: R118.1 U5.L2 U13.M22 | length 31.5
  Top Layer w0.12: U5.L2@47.63,47.94 v1(48.03,48.34) ; v1(48.56,39.44) 48.16,39.84 46.19,39.84 46.11,39.92 46.11,40.12 46.24,40.25 48.58,40.25 49.11,39.72 50.04,39.72 50.23,39.53 50.23,35.84 U13.M22@50.08,35.69
  Bottom Layer w0.12: R118.1@46.82,56.41 46.82,54.859 47.59,54.089 47.59,49.071 47.817,48.844 48.03,48.631 v1(48.03,48.34) 48.321,48.34 48.681,47.98 49.35,47.98 49.55,48.18 49.67,48.18 49.74,48.11 49.74,40.619 v1@48.56,39.44
DDR_DQ0: U5.A2 U13.E22 | length 24
  Top Layer w0.09: 46.21,36.5 46.331,36.379 46.331,36.294 ; 46.33,36.086 46.33,36.294 ; 46.331,36.086 46.331,35.959 U13.E22@46.58,35.71
  Top Layer w0.12: v1(44.83,37.59) 45.129,37.59 45.39,37.329 45.39,36.94 45.56,36.77 45.94,36.77 46.21,36.5 ; U13.E22@46.58,35.69 U13.E22@46.58,35.71 ; v1(47.23,55.54) U5.A2@47.63,55.94
  Signal Layer 2 w0.12: v1@44.84,37.595 v1@44.89,37.595
  Signal Layer 2 w0.127: v1@44.84,37.595 44.28,37.595 44.02,37.855 44.02,40.635 46.74,43.355 46.74,44.685 46.85,44.795 46.85,45.515 46.74,45.625 46.74,52.931 47.604,53.795 47.604,54.442 47.24,54.806 v1@47.24,55.545
DDR_DQ1: U5.C3 U13.F22 | length 25.1
  Top Layer w0.09: 46.83,36.67 47.08,36.42 U13.F22@47.08,35.69
  Top Layer w0.12: v1@45.8,37.66 46.01,37.66 46.14,37.53 46.14,37.36 46.83,36.67 ; U5.C3@48.43,54.34 48.8,53.97 v1(48.8,53.95)
  Signal Layer 2 w0.127: v1@45.76,37.665 45.76,38.045 44.95,38.855 44.95,39.345 50.16,44.555 50.16,44.825 49.99,44.995 49.35,44.995 49.07,45.275 49.07,45.545 49.3,45.775 49.55,45.775 49.82,46.045 49.82,46.425 49.63,46.615 48.99,46.615 48.59,47.015 48.59,47.265 49.206,47.881 49.206,49.821 49.42,50.035 49.42,50.905 48.386,51.938 48.386,53.31 48.635,53.558 48.635,53.78 v1@48.81,53.955
  other v1: 45.75,37.66
DDR_DQ2: U5.A7 U13.H21 | length 25.4
  Top Layer w0.09: v1(47.75,37.83) 48.335,37.245 ; U13.H21@48.08,35.19 48.08,35.2 48.335,35.455 ; 48.33,35.455 48.33,37.245
  Top Layer w0.12: U5.A7@51.63,55.94 v1(52.03,55.54)
  Signal Layer 2 w0.127: v1@47.76,37.835 47.76,38.365 48.164,38.769 48.164,39.615 48.947,40.398 51.253,40.398 53.297,42.442 53.297,51.998 52.44,52.855 52.44,55.145 v1@52.04,55.545
DDR_DQ3: U5.C2 U13.E21 | length 24.1
  Top Layer w0.09: 45.71,36.5 45.83,36.38 45.83,35.58 45.97,35.44 46.33,35.44 U13.E21@46.58,35.19
  Top Layer w0.12: v1(45.03,37.13) 45.03,36.93 45.46,36.5 45.71,36.5 ; v1(47.23,53.94) U5.C2@47.63,54.34
  Signal Layer 2 w0.12: v1@45.04,37.135 v1@45.09,37.135
  Signal Layer 2 w0.127: v1@45.04,37.135 43.78,37.135 43.54,37.375 43.54,43.175 45.5,45.135 45.5,46.895 45.74,47.135 45.74,48.195 45.63,48.305 45.63,53.535 46.04,53.945 v1@47.24,53.945
DDR_DQ4: U5.B8 U13.J21 | length 26.2
  Top Layer w0.09: U13.J21@48.583,35.185 48.583,35.339 48.83,35.586 48.83,35.915 48.773,35.972 ; v1(48.73,37.69) 48.73,37.399 48.77,37.359 48.77,35.972
  Top Layer w0.12: U5.B8@52.43,55.245 U5.B8@52.43,55.14 v1(52.83,54.74)
  Signal Layer 2 w0.127: v1@48.735,37.69 48.95,37.475 49.524,37.475 50.307,38.258 50.307,38.435 51.37,39.498 53.213,39.498 54.36,40.645 54.36,41.364 55.59,42.594 55.59,42.75 ; v1@52.84,54.745 55.593,51.992 55.593,42.75
DDR_DQ5: U5.C8 U13.J22 | length 25
  Top Layer w0.09: v1(48.25,37.83) 48.25,37.61 48.58,37.28 U13.J22@48.58,35.69
  Top Layer w0.12: U5.C8@52.43,54.34 52.43,54.32 v1@52.81,53.94
  Signal Layer 2 w0.127: v1@48.26,37.835 48.501,38.076 49.521,38.076 49.88,38.435 49.88,38.955 50.85,39.925 52.67,39.925 53.11,40.365 53.11,40.635 52.83,40.915 52.83,41.327 53.188,41.685 54.05,41.685 54.35,41.985 54.35,42.465 54.97,43.085 54.97,51.842 v1@52.867,53.945
  other v1: 52.83,53.94
DDR_DQ6: U5.D7 U13.H22 | length 25.4
  Top Layer w0.09: v1(47.73,37.02) v1@47.835,36.915 ; 47.83,35.895 v1@47.83,36.915 ; 47.835,35.895 48.08,35.65 U13.H22@48.08,35.69
  Top Layer w0.12: v1@51.25,53.16 U5.D7@51.63,53.54
  Signal Layer 2 w0.127: v1@47.74,37.025 47.38,37.385 47.38,39.005 47.72,39.345 47.72,40.03 48.515,40.825 51.014,40.825 52.87,42.681 52.87,47.865 52.68,48.055 52.33,48.055 52.13,48.255 52.13,48.395 52.31,48.575 52.64,48.575 52.79,48.725 52.79,49.685 52.53,49.945 51.87,49.945 51.7,50.115 51.7,50.545 51.82,50.665 52.49,50.665 52.67,50.845 52.67,51.265 51.75,52.185 51.5,52.185 51.24,52.445 v1@51.24,53.145
  other v1: 51.23,53.14
DDR_DQ7: U5.A3 U13.G21 | length 25.9
  Top Layer w0.09: 46.66,36.49 46.83,36.32 46.83,36.086 46.828,36.084 46.828,35.796 46.83,35.794 46.83,35.586 ; 46.83,35.586 46.83,35.554 46.943,35.44 46.976,35.44 ; 46.979,35.44 47.181,35.44 ; 47.186,35.44 47.323,35.44 47.573,35.19 U13.G21@47.58,35.19
  Top Layer w0.12: v1(45.8,37.14) 46.01,37.14 46.66,36.49 ; v1(48.03,55.54) U5.A3@48.43,55.94
  Signal Layer 2 w0.127: v1@45.81,37.145 45.61,37.145 45.33,37.425 45.33,37.89 45.19,38.03 44.595,38.03 44.45,38.175 44.45,39.953 45.621,41.124 45.621,41.556 45.83,41.765 46.262,41.765 48.655,44.158 48.655,44.58 47.65,45.585 47.65,49.995 48.2,50.545 48.2,51.445 47.78,51.865 47.78,53.298 47.96,53.477 47.96,53.487 48.04,53.568 v1@48.04,55.545
DDR_DQ8: U5.F2 U13.T21 | length 26
  Top Layer w0.09: 51.48,38.61 51.63,38.46 51.63,36 51.83,35.795 51.83,35.435 ; 51.835,35.435 U13.T21@52.08,35.19
  Top Layer w0.12: U5.F2@47.63,51.94 47.23,51.54 44.56,51.54 43.62,50.6 43.62,42.34 45.25,40.71 49.644,40.71 50.83,39.524 50.83,39.25 51.45,38.63
DDR_DQ9: U5.E3 U13.U21 | length 26.2
  Top Layer w0.09: 52.33,35.435 52.33,37.02 ; 52.335,35.435 U13.U21@52.58,35.19
  Top Layer w0.12: U5.E3@48.43,52.74 48.02,52.33 48.02,50.93 48.21,50.74 49.41,50.74 49.61,50.54 49.61,47.932 49.4,47.722 49.4,43.722 48.74,43.062 48.74,42.68 48.45,42.39 46.66,42.39 46.56,42.29 46.56,42.08 46.67,41.97 50.166,41.97 52.09,40.046 52.09,39.772 52.717,39.145 52.717,37.397 52.34,37.02
DDR_DQ10: U5.G2 U13.T22 | length 25.9
  Top Layer w0.09: 51.83,37.43 51.83,36.077 52.08,35.827 U13.T22@52.08,35.69
  Top Layer w0.12: U5.G2@47.63,51.14 47.63,50.92 47.22,50.51 47.22,50.1 47.06,49.94 46.55,49.94 45.435,48.825 44.425,48.825 44.13,48.53 44.13,48.1 44.3,47.93 44.83,47.93 44.95,47.81 44.95,47.52 44.8,47.37 44.41,47.37 44.04,47 44.04,44.62 44.29,44.37 44.55,44.37 44.72,44.2 44.72,43.74 44.56,43.58 44.27,43.58 44.04,43.35 44.04,42.514 45.424,41.13 49.818,41.13 51.25,39.698 51.25,39.424 51.877,38.797 51.877,37.452 51.855,37.43
DDR_DQ11: U5.F7 U13.W21 | length 25.8
  Top Layer w0.09: U13.W21@53.58,35.19 53.713,35.19 53.963,35.44 54.193,35.44 54.33,35.577 54.33,36.351 ; 54.335,36.351 54.457,36.473
  Top Layer w0.12: U5.F7@51.63,51.94 52.03,51.54 54.1,51.54 54.6,52.04 55.356,52.04 55.933,51.463 55.933,50.977 56.45,50.46 56.45,48.57 56.94,48.08 56.94,47.496 56.497,47.053 56.497,46.823 56.94,46.38 56.94,45.786 56.51,45.356 56.51,45.06 56.94,44.63 56.94,44.106 56.61,43.776 56.61,43.26 57,42.87 57,42.01 57.11,41.9 57.744,41.9 58.14,41.504 58.14,39.81 55.52,37.19 55.174,37.19 54.457,36.473
DDR_DQ12: U5.H8 U13.W23 | length 25.1
  Top Layer w0.09: U13.W23@53.58,36.19 53.58,36.44 54.245,37.105
  Top Layer w0.12: U5.H8@52.43,50.34 52.85,49.92 55.73,49.92 56.03,49.62 56.03,48.396 56.52,47.906 56.52,47.67 56.03,47.18 56.03,46.696 56.52,46.206 56.52,45.96 56.03,45.47 56.03,44.946 56.52,44.456 56.52,44.28 56.03,43.79 56.03,42.99 56.182,42.838 56.438,42.838 56.58,42.696 56.58,42.3 56.487,42.207 55.92,42.207 55.707,42.42 55.336,42.42 54.57,41.654 54.57,41.306 55.148,40.728 55.426,40.728 55.758,41.06 57.2,41.06 57.3,40.96 57.3,40.16 54.245,37.105
DDR_DQ13: U5.H3 U13.T23 | length 25.3
  Top Layer w0.09: U13.T23@52.08,36.19 52.08,37.31
  Top Layer w0.12: U5.H3@48.43,50.34 49.02,50.34 49.19,50.17 49.19,48.106 48.98,47.896 48.98,43.896 47.894,42.81 46.64,42.81 46.28,43.17 46.08,43.17 45.78,42.87 45.49,42.87 45.2,43.16 44.69,43.16 44.469,42.939 44.469,42.679 45.598,41.55 49.992,41.55 51.67,39.872 51.67,39.598 52.297,38.971 52.297,37.507 52.1,37.31
DDR_DQ14: U5.H7 U13.W22 | length 24.5
  Top Layer w0.09: U13.W22@53.58,35.69 53.31,35.96 53.31,36.53 54.34,37.56 54.34,37.794 54.355,37.809
  Top Layer w0.12: U5.H7@51.63,50.34 50.87,49.58 50.87,48.84 51.08,48.63 51.08,44.18 51.08,43.476 52.291,42.265 52.99,42.265 53.17,42.445 53.17,42.9 53.32,43.05 54.47,43.05 54.78,42.74 54.78,42.458 54.15,41.828 54.15,41.132 55.362,39.92 55.65,39.92 55.81,40.08 55.81,40.5 55.95,40.64 56.69,40.64 56.84,40.49 56.84,40.294 55.746,39.2 55.477,39.2 55.198,38.921 55.198,38.652 54.826,38.28 54.557,38.28 54.355,38.078 54.355,37.809
DDR_DQ15: U5.F8 U13.Y21 | length 24.2
  Top Layer w0.09: U13.Y21@54.079,35.192 54.216,35.192 54.464,35.44 54.692,35.44 54.83,35.578 54.83,36.345 ; 54.835,36.345 54.97,36.48 55.404,36.48 55.517,36.593
  Top Layer w0.12: U5.F8@52.43,51.94 52.81,52.32 53.43,52.32 53.457,52.347 ; 53.444,52.36 53.544,52.46 55.55,52.46 57.42,50.59 57.42,42.818 58.56,41.678 58.56,39.636 55.517,36.593
DDR_DQM0: U5.D3 U13.H23 | length 24.7
  Top Layer w0.09: 47.39,37.997 47.39,37.68 47.697,37.373 47.897,37.373 48.08,37.19 U13.H23@48.08,36.19
  Top Layer w0.12: v1(45.57,38.86) 45.99,38.44 46.947,38.44 47.39,37.997 ; U5.D3@48.41,53.543 48.387,53.52 48.41,53.52 v1(48.8,53.13)
  Signal Layer 2 w0.127: v1@45.58,38.865 45.58,39.371 48.334,42.125 49.65,42.125 49.78,42.255 49.78,42.475 49.67,42.585 49.22,42.585 49.087,42.718 49.087,42.878 49.564,43.355 49.82,43.355 50.587,44.122 50.587,45.002 50.247,45.342 50.247,46.045 50.41,46.208 50.41,46.625 49.993,47.042 49.493,47.042 49.347,47.188 49.347,47.418 49.633,47.705 49.633,49.645 49.847,49.858 49.847,51.082 48.813,52.115 v1@48.813,53.134
DDR_DQM1: U5.E7 U13.V22 | length 26.8
  Top Layer w0.09: 50.675,43.308 50.675,44.61 ; U13.V22@53.08,35.69 53.08,36.62 53.935,37.475 53.935,37.728
  Top Layer w0.12: U5.E7@51.63,52.74 50.98,52.74 50.66,53.06 50.66,53.87 50.35,54.18 49.84,54.18 49.53,53.87 49.53,53 50.66,51.87 50.66,49.98 50.62,49.94 50.62,48.43 50.66,48.39 50.66,43.302 52.117,41.845 53.539,41.845 53.73,41.654 53.73,40.53 53.933,40.327 54.362,40.327 54.807,39.882 54.807,39.124 53.935,38.252 53.935,37.728
DDR_DQS0_N: U5.B7 U13.G23 | length 24.7
  Top Layer w0.1: v1(46.98,37.74) 46.85,37.61 46.85,37.45 47.09,37.21 47.09,37.103 47.58,36.613 U13.G23@47.58,36.19 ; U5.B7@51.63,55.14 v1(52.03,54.74)
  Signal Layer 2 w0.09: v1@46.99,37.76 46.85,37.9 46.85,39.738 48.598,41.486 50.467,41.486 50.965,41.985 50.965,42.635 50.733,42.868 50.733,43.162 50.988,43.417 51.348,43.417 51.72,43.79 51.72,44.345 51.225,44.839 51.225,46.895 50.485,47.635 50.485,53.665 50.565,53.745 51.525,53.745 51.75,53.97 51.75,54.47 v1@52.025,54.745
DDR_DQS0_P: U5.C7 U13.G22 | length 25.4
  Top Layer w0.1: v1(46.48,37.74) 46.62,37.6 46.62,37.355 46.86,37.115 46.86,37.007 47.35,36.517 47.35,36.314 47.3,36.264 47.3,35.97 U13.G22@47.58,35.69 ; v1(51.23,54.74) U5.C7@51.63,54.34
  Signal Layer 2 w0.09: v1@46.49,37.765 46.61,37.885 46.61,39.823 48.503,41.716 50.371,41.716 50.735,42.08 50.735,42.54 50.503,42.772 50.503,43.258 50.892,43.647 51.252,43.647 51.49,43.885 51.49,44.25 50.995,44.744 50.995,46.799 50.255,47.539 50.255,53.76 50.47,53.975 51.43,53.975 51.52,54.065 51.52,54.465 v1@51.24,54.745
  Signal Layer 2 w0.1: v1@51.24,54.745 v1@51.28,54.745
DDR_DQS1_N: U5.G3 U13.U23 | length 25.2
  Top Layer w0.1: U5.G3@48.43,51.14 48.71,51.42 49.005,51.42 49.315,51.73 49.8,51.73 50.02,51.51 50.02,47.69 49.81,47.48 49.81,47.13 50.02,46.92 50.02,46.755 49.81,46.545 49.81,46.22 50.02,46.01 50.02,45.855 49.81,45.645 49.81,45.33 50.02,45.12 50.02,45.005 49.81,44.795 49.81,44.48 50.02,44.27 50.02,43.305 49.955,43.24 49.498,43.24 49.167,42.909 49.167,42.615 49.401,42.38 50.677,42.38 50.8,42.257 50.8,41.916 51.056,41.66 51.397,41.66 51.548,41.508 51.548,41.167 51.955,40.76 52.285,40.76 52.73,41.205 52.945,41.205 53.09,41.06 53.09,40.915 52.5,40.325 52.5,39.942 52.755,39.687 54.04,39.687 54.167,39.56 54.167,39.389 54.06,39.282 53.372,39.282 53.127,39.037 53.127,38.568 53.295,38.4 53.295,37.972 53.127,37.804 53.127,37.382 52.63,36.885 52.63,36.24 U13.U23@52.58,36.19
DDR_DQS1_P: U5.F3 U13.U22 | length 26.2
  Top Layer w0.1: U5.F3@48.43,51.94 48.72,51.65 48.91,51.65 49.22,51.96 49.895,51.96 50.25,51.605 50.25,47.595 50.04,47.385 50.04,47.225 50.25,47.015 50.25,46.66 50.04,46.45 50.04,46.315 50.25,46.105 50.25,45.76 50.04,45.55 50.04,45.425 50.25,45.215 50.25,44.91 50.04,44.7 50.04,44.575 50.25,44.365 50.25,43.21 50.05,43.01 49.593,43.01 49.397,42.813 49.397,42.71 49.497,42.61 50.772,42.61 51.03,42.352 51.03,42.011 51.151,41.89 51.492,41.89 51.786,41.596 51.786,41.255 52.05,40.99 52.19,40.99 52.635,41.435 53.04,41.435 53.32,41.155 53.32,40.82 52.73,40.23 52.73,40.037 52.85,39.917 54.135,39.917 54.397,39.655 54.397,39.294 54.155,39.052 53.468,39.052 53.357,38.942 53.357,38.663 53.525,38.495 53.525,37.876 53.357,37.708 53.357,37.287 52.86,36.79 52.86,35.97 U13.U22@52.58,35.69
DDR_ODT: R122.1 U5.K1 U13.L22 | length 31.3
  Top Layer w0.12: U5.K1@46.83,48.74 v1(47.23,48.34) ; v1(48.82,38.93) 49.19,39.3 49.85,39.3 49.96,39.19 49.96,39.08 49.75,38.87 49.75,38.704 49.957,38.497 49.957,36.067 U13.L22@49.58,35.69
  Bottom Layer w0.12: R122.1@44.68,54.22 44.73,54.27 45.52,54.27 45.89,53.9 46.329,53.9 47.02,53.209 47.02,49.439 46.87,49.289 46.87,48.7 v1(47.23,48.34) 47.479,48.34 47.904,47.915 48.235,47.915 48.565,47.585 49.175,47.585 49.47,47.29 49.47,40.943 48.167,39.64 46.06,39.64 45.86,39.44 45.86,39.099 46.099,38.86 46.297,38.86 46.575,38.582 46.73,38.582 46.83,38.682 46.83,38.94 47.01,39.12 47.23,39.12 47.34,39.01 47.34,38.74 47.47,38.61 48.11,38.61 48.43,38.93 v1(48.82,38.93)
DDR_RASN: R115.1 U5.J3 U13.N21 | length 30.1
  Top Layer w0.09: U13.N21@50.58,35.19 50.83,34.93 v1@50.83,34.32 ; v1(50.78,34.26) v1@50.84,34.32
  Top Layer w0.1: U5.J3@48.416,49.52 U5.J3@48.418,49.521
  Top Layer w0.12: U5.J3@48.43,49.54 v1(48.83,49.94)
  Bottom Layer w0.12: R115.1@50.06,56.41 50.06,55.37 49.19,54.5 49.19,50.78 48.83,50.42 v1(48.83,49.94) 49.09,49.94 50.51,51.36 50.75,51.36 50.82,51.29 50.82,50.641 51.02,50.441 51.02,49.74 50.55,49.27 50.55,40.94 50.62,40.87 50.62,38.93 50.52,38.83 50.52,38.17 50.78,37.91 50.78,37.403 50.5,37.123 50.5,36.6 50.42,36.52 49.92,36.52 49.76,36.36 49.76,36.251 49.91,36.101 50.459,36.101 50.54,36.02 50.54,35.068 50.75,34.858 v1@50.75,34.26
DDR_RESETN: R37.2 U5.T2 U13.D20 | length 16.7
  Top Layer w0.09: 45.226,36.413 45.33,36.309 45.33,35.57 45.46,35.44 45.688,35.44 45.83,35.3 45.83,34.94 U13.D20@46.08,34.69
  Top Layer w0.12: v1(42.15,43.38) 43.09,42.44 43.09,41.89 44.33,40.65 44.33,37.3 44.339,37.3 45.226,36.413 ; v1(45.32,43.93) 45.66,43.59 ; 45.66,43.58 47.28,43.58 ; 47.28,43.59 U5.T2@47.63,43.94
  Bottom Layer w0.12: v1(42.15,43.38) 42.15,43.75 42.25,43.85 45.12,43.85 45.2,43.93 v1(45.32,43.93)
DDR_WEN: R117.1 U5.L3 U13.M20 | length 30.2
  Top Layer w0.09: v1(49.65,33.73) 50.08,34.16 U13.M20@50.08,34.69
  Top Layer w0.12: U5.L3@48.43,47.94 v1(48.83,48.34)
  Bottom Layer w0.12: R117.1@47.9,56.41 47.9,55.93 47.66,55.69 47.66,55.15 48.01,54.8 48.01,49.669 48.43,49.249 48.43,48.74 v1(48.83,48.34) ; 48.4,36.9 49.044,36.9 49.746,37.603 49.746,37.756 49.56,37.942 49.56,38.26 49.68,38.38 49.68,38.689 49.474,38.895 ; 48.44,36.9 48.4,36.9 48.21,36.9 48.151,36.841 48.151,36.671 48.341,36.481 48.669,36.481 48.748,36.402 48.748,36.074 49.69,35.133 49.69,34.73 49.97,34.45 49.97,34.33 49.97,33.81 49.89,33.73 v1(49.65,33.73) v1@49.65,33.791 ; v1@48.797,48.33 49.17,48.33 49.29,48.45 49.29,48.71 49.43,48.85 49.86,48.85 50.01,48.7 50.01,40.295 49.11,39.395 49.11,39.2 49.42,38.89 49.469,38.89
DSCL: CN9.15 R98.1 U14.49 U33.3 | length 32.3
  Top Layer w0.1: U14.49@73.425,22.425 73.425,21.55 75,19.975 76.125,19.975 76.725,19.375 76.725,17.083 78.958,14.85 83.121,14.85 85.625,12.346 85.625,10.825 85.075,10.275 R98.1@84.975,10.275 84.975,10.075 85.408,10.075 87.283,8.2 89.208,8.2 90.333,7.075 90.933,7.075 91.058,6.95 91.8,6.95 v1(92.1,7.25) CN9.15@93.5,7.25
  Bottom Layer w0.1: U33.3@90.7,6.85 91.7,6.85 v1(92.1,7.25)
DSDA: CN9.16 R97.1 U14.48 U33.6 | length 36.2
  Top Layer w0.1: U14.48@72.925,22.425 72.925,21.925 73.225,21.625 73.225,21.467 74.917,19.775 76.042,19.775 76.525,19.292 76.525,17 78.875,14.65 83.039,14.65 85.425,12.264 85.425,10.975 85.225,10.775 84.55,10.775 84.05,10.275 R97.1@83.925,10.275 84.4,9.8 85.4,9.8 87.2,8 89.125,8 90.25,6.875 90.85,6.875 90.975,6.75 v1(92.1,6.75) CN9.16@93.5,6.75
  Bottom Layer w0.1: U33.6@89.75,7.85 89.912,7.85 90.225,7.537 90.225,6.625 90.475,6.375 91.725,6.375 v1(92.1,6.75)
DSI_CK_N: CN4.5 U13.A16 | length 26.4
  Top Layer w0.09: 30.337,36.226 30.337,36.233
  Top Layer w0.1: CN4.5@20.675,36 21.215,36 21.584,36.369 23.436,36.369 23.805,36 CN4.5@24.425,36 25.053,36 25.424,36.371 27.117,36.371 v1(27.245,36.243) ; v1(29.897,36.24) 30.029,36.373 30.191,36.373 30.337,36.226 30.525,36.039 30.525,35.52 32.981,33.064 40.181,33.064 40.555,32.69 U13.A16@44.58,32.69
  Bottom Layer w0.1: v1(27.245,36.243) 27.378,36.375 29.762,36.375 v1(29.897,36.24)
DSI_CK_P: CN4.6 U13.B16 | length 27.1
  Top Layer w0.09: 43.697,32.93 43.707,32.94 44.83,32.94 U13.B16@45.08,32.69
  Top Layer w0.1: CN4.6@20.675,37 21.202,37 21.604,36.599 23.394,36.599 23.795,37 CN4.6@24.425,37 25.044,37 25.443,36.601 27.103,36.601 v1(27.245,36.743) ; v1(29.897,36.74) 30.034,36.603 30.286,36.603 30.755,36.134 30.755,35.615 33.076,33.294 40.276,33.294 40.64,32.93 43.697,32.93
  Bottom Layer w0.1: v1(27.245,36.743) 27.383,36.605 29.762,36.605 v1(29.897,36.74)
DSI_D0_N: CN4.8 U13.B15 | length 27.8
  Top Layer w0.09: 43.698,32.2 43.708,32.19 U13.B15@45.08,32.19
  Top Layer w0.1: CN4.8@20.675,39 21.223,39 21.608,39.385 23.423,39.385 23.808,39 CN4.8@24.425,39 25.053,39 25.405,39.352 25.573,39.352 32.44,32.485 39.71,32.485 39.995,32.2 43.698,32.2
DSI_D0_P: CN4.9 U13.C15 | length 28.5
  Top Layer w0.09: 43.699,32.43 43.709,32.44 45.33,32.44 U13.C15@45.58,32.19
  Top Layer w0.1: CN4.9@20.675,40 21.232,40 21.617,39.615 23.378,39.615 23.763,40 CN4.9@24.425,40 25.082,40 25.5,39.582 25.668,39.582 32.535,32.715 39.805,32.715 40.09,32.43 43.699,32.43
DSI_D1_N: CN4.2 U13.A17 | length 25.1
  Top Layer w0.09: 43.7,33.2 43.71,33.19 U13.A17@44.58,33.19
  Top Layer w0.1: CN4.2@20.675,33 21.208,33 21.593,33.385 23.418,33.385 23.803,33 CN4.2@24.425,33 25.034,33 25.405,33.371 27.861,33.371 28.332,33.842 29.311,33.842 v1(29.446,33.707) ; v1(33.313,33.707) 33.448,33.842 40.544,33.842 41.186,33.2 43.7,33.2
  Bottom Layer w0.1: v1(29.446,33.707) 29.581,33.842 33.178,33.842 v1(33.313,33.707)
DSI_D1_P: CN4.3 U13.B17 | length 25.7
  Top Layer w0.09: 43.697,33.43 43.707,33.44 44.83,33.44 U13.B17@45.08,33.19
  Top Layer w0.1: CN4.3@20.675,34 21.221,34 21.606,33.615 23.38,33.615 23.765,34 CN4.3@24.425,34 25.047,34 25.447,33.601 27.766,33.601 28.237,34.072 29.311,34.072 v1(29.446,34.207) ; v1(33.313,34.207) 33.448,34.072 40.639,34.072 41.281,33.43 43.697,33.43
  Bottom Layer w0.1: v1(29.446,34.207) 29.581,34.072 33.178,34.072 v1(33.313,34.207)
DSI_LCD_BL_CTRL: CN4.19 U13.C19 | length 35.9
  Top Layer w0.09: 33.424,45.27 34.759,45.27 35.224,45.27 38.074,42.42 38.301,42.42 38.302,42.419 39.973,42.419 40.172,42.22 41.011,42.22 42.76,40.471 42.76,36.155 v4(43.202,35.712)
  Top Layer w0.1: CN4.19@24.425,50 25.025,50 25.65,49.375 25.65,48.725 25.783,48.592 25.783,48.335 27.112,47.005 28.675,47.005 29.275,46.405 29.275,45.475 29.6,45.15 33.309,45.15 33.424,45.265 ; U13.C19@45.58,34.19 v2(45.83,33.94)
  Top Layer w0.3: CN4.19@20.675,50 CN4.19@24.425,50
  Signal Layer 1 w0.09: v4(43.202,35.712) 43.532,35.712 44.454,34.79 44.81,34.79 45.35,34.25 45.52,34.25 v2(45.83,33.94)
DSI_LCD_INT: CN4.17 U13.A14 | length 39.2
  Top Layer w0.1: CN4.17@24.425,48 25.551,48 26.85,46.701 26.85,45.4 27.1,45.15 28.35,45.15 28.525,44.975 28.525,43.3 28.275,43.05 28.275,42.425 28.525,42.175 30.9,42.175 33.6,44.875 34.237,44.875 35.38,43.732 35.38,41.994 38.305,39.069 v1(38.305,38.34) ; v1(41.38,31.74) 41.68,31.44 42.075,31.44 42.325,31.69 U13.A14@44.58,31.69
  Top Layer w0.3: CN4.17@20.675,48 CN4.17@24.425,48
  Bottom Layer w0.1: v1(38.305,38.34) 38.305,37.865 38.83,37.34 38.83,35.776 40.04,34.566 40.04,33.533 41.38,32.193 v1(41.38,31.74)
DSI_RESET: CN4.20 R11.2 U13.D19 | length 38.5
  Top Layer w0.1: R11.2@19.625,52.325 20.075,52.325 20.675,51.725 CN4.20@20.675,51 ; CN4.20@24.425,51 24.425,50.825 25.195,50.825 25.983,50.037 25.983,48.417 27.195,47.205 28.758,47.205 29.475,46.488 29.475,45.558 29.683,45.35 33.226,45.35 33.341,45.465 33.507,45.465 33.517,45.465 34.84,45.465 35.305,45.465 38.155,42.615 38.82,42.615 ; v4(43.03,36.466) 43.105,36.54 43.105,40.402 41.092,42.415 40.253,42.415 40.054,42.614 38.821,42.614 ; v2(45.83,34.44) U13.D19@46.08,34.19 ; 38.82,42.615 38.821,42.614
  Top Layer w0.3: CN4.20@20.675,51 CN4.20@24.425,51
  Signal Layer 1 w0.09: v4(43.03,36.466) 43.048,36.466 44.533,34.98 44.889,34.98 45.429,34.44 v2(45.83,34.44)
DSI_TE: CN4.18 U13.B14 | length 40
  Top Layer w0.09: 44.28,31.94 44.83,31.94 U13.B14@45.08,31.69
  Top Layer w0.1: CN4.18@24.425,49 25.085,49 25.583,48.503 25.583,48.252 27.05,46.784 27.05,45.483 27.183,45.35 28.433,45.35 28.725,45.058 28.725,43.217 28.475,42.967 28.475,42.508 28.608,42.375 30.817,42.375 33.517,45.075 34.32,45.075 35.58,43.815 35.58,42.077 38.78,38.877 v1(38.78,37.967) ; v1(41.93,31.79) 42.08,31.94 44.28,31.94
  Top Layer w0.3: CN4.18@20.675,49 CN4.18@24.425,49
  Bottom Layer w0.1: v1(38.78,37.967) 39.03,37.717 39.03,35.859 40.24,34.649 40.24,33.616 41.93,31.926 v1(41.93,31.79)
ETH_CLK: R69.2 U13.Y8 | length 74.2
  Top Layer w0.1: v2(53.83,28.94) U13.Y8@54.08,28.69
  Top Layer w0.13: R69.2@23.825,23.675 24.275,23.675 24.925,23.025 v1(25.175,23.025)
  Signal Layer 1 w0.1: v2(53.83,28.94) 53.941,28.94 54.216,29.215 57.855,29.215 58.28,28.79 58.28,27.665 v1(59.13,26.815)
  Signal Layer 2 w0.13: v1(25.175,23.025) 25.45,22.75 26.15,22.75 28.95,19.95 28.95,13.27 29.395,12.825 33.245,12.825 35.53,15.11 38.224,15.11 39.129,16.015 41.793,16.015 43.768,14.04 44.828,14.04 45.413,13.455 46.459,13.455 47.573,12.341 48.45,12.341 48.725,12.616 48.725,14.946 49.439,15.66 50.901,15.66 51.665,14.896 51.665,13.18 51.815,13.03 53.347,13.03 53.907,13.59 55.482,13.59 56.731,12.341 57.518,12.341 57.965,12.788 57.965,13.628 59.27,14.933 59.27,17.347 58.85,17.767 58.85,18.345 57.985,19.21 57.985,20.728 58.85,21.593 58.85,25.505 59.13,25.785 v1(59.13,26.815)
ETH_CLK125: R153.1 U13.Y6 | length 68.6
  Top Layer w0.1: U13.Y6@54.08,27.69 v2(54.33,27.94)
  Signal Layer 1 w0.1: v2(54.33,27.94) 54.605,28.215 54.955,28.215 56.43,26.74 57.626,26.74 57.831,26.535 57.831,25.719 62.625,20.925 62.625,19.725 59.975,17.075 58.733,17.075 57.758,16.1 55.32,16.1 v1(55.28,16.14)
  Signal Layer 2 w0.13: v1(32.338,15.5) 38.063,15.5 38.968,16.405 41.954,16.405 43.67,14.69 47.917,14.69 50.043,16.815 51.268,16.815 51.625,16.458 51.625,16.133 51.985,15.773 51.985,15.738 52.055,15.668 52.055,13.695 52.33,13.42 53.186,13.42 53.746,13.98 54.785,13.98 55.38,14.575 57.23,14.575 57.35,14.695 57.35,15.331 57.156,15.525 55.376,15.525 55.28,15.621 v1(55.28,16.14)
  Bottom Layer w0.13: R153.1@26.7,23.85 29.799,23.85 31.375,22.274 31.375,21.447 32.225,20.597 32.225,19.933 32.05,19.758 32.05,15.788 v1(32.338,15.5)
ETH_GTX_CLK: U13.AB2 U18.20 | length 71
  Top Layer w0.09: U13.AB2@55.08,25.69 55.33,25.94 56.28,25.94
  Top Layer w0.1: 38.83,16.965 38.834,16.961
  Top Layer w0.13: U18.20@31.75,24.55 31.76,24.54 35.923,24.54 38.845,21.618 38.845,14.98 v1(39,14.825) ; 56.28,25.94 56.925,25.94 57.115,25.75 58.633,25.75 58.887,26.004 61.444,26.004 v1(62.03,26.59)
  Signal Layer 2 w0.13: v1(39,14.825) 39,13.441 39.736,12.705 40.05,12.705 40.4,13.055 40.4,14.61 40.7,14.91 41.44,14.91 41.875,14.475 41.875,13.13 42.3,12.705 43.547,12.705 44.132,13.29 44.518,13.29 45.103,12.705 46.148,12.705 47.262,11.591 48.782,11.591 49.475,12.284 49.475,14.635 49.75,14.91 50.59,14.91 50.915,14.585 50.915,11.844 51.168,11.591 54.74,11.591 55.429,12.28 55.731,12.28 56.42,11.591 57.828,11.591 58.715,12.478 58.715,13.318 60.02,14.623 60.02,16.764 60.165,16.909 60.165,25.267 61.488,26.59 v1(62.03,26.59)
ETH_MDC: R76.1 U13.AA6 U18.13 | length 53.8
  Top Layer w0.1: U18.13@31.75,21.75 32.625,21.75 32.9,21.475 32.9,21.275 32.975,21.2 34.05,21.2 34.5,21.65 R76.1@34.675,21.65 ; v1(33.575,16.525) 33.575,17.325 33.675,17.425 33.675,18.003 35.155,19.483 35.155,21.095 R76.1@34.6,21.65 ; U13.AA6@54.58,27.69 v2(54.83,27.44)
  Signal Layer 1 w0.1: v2(54.83,27.44) 56.195,26.075 56.95,26.075 61.325,21.7 61.325,18.875 59.8,17.35 58.6,17.35 57.55,16.3 56.42,16.3 v1(56.205,16.515)
  Signal Layer 2 w0.1: v1(33.575,16.525) 33.825,16.275 37.756,16.275 38.931,17.45 43.35,17.45 43.65,17.15 49.195,17.15 49.625,17.58 49.848,17.58 ; 49.87,17.602 50.343,18.075 51.95,18.075 52.39,17.635 52.39,16.95 52.75,16.59 52.75,16.055 53.005,15.8 53.858,15.8 54.963,16.905 54.97,16.912 55.808,16.912 v1(56.205,16.515)
ETH_MDINT: R65.1 U13.AC8 U18.31 | length 68.3
  Top Layer w0.09: U13.AC8@55.58,28.69 55.78,28.69 55.81,28.72 56.15,28.72 56.18,28.69 v4@56.38,28.69
  Top Layer w0.1: R65.1@25.85,25.3 25.85,24.675 v1(25.975,24.55) U18.31@26.85,24.55 ; v4@56.38,28.69 v4(56.405,28.665)
  Signal Layer 1 w0.1: v4(56.405,28.665) 56.23,28.84 55.755,28.84 55.555,28.64 55.555,28.315 56.655,27.215 57.755,27.215 58.955,26.015 59.655,26.015 60.03,26.39 60.03,27.34 59.805,27.565 59.805,27.965 v1(59.98,28.14)
  Signal Layer 2 w0.1: v1(25.975,24.55) 26.775,23.75 26.775,23.025 29.75,20.05 30.225,20.05 32.935,17.34 36.28,17.34 v1(36.255,17.365)
  Bottom Layer w0.1: v1(36.255,17.365) 36.255,18.485 36.95,19.18 36.95,20.835 37.805,21.69 38.2,21.69 38.405,21.485 38.405,21.12 39.2,20.325 44.005,20.325 44.905,19.425 46.952,19.425 47,19.473 47.375,19.098 47.375,17.025 47.8,16.6 49.992,16.6 50.442,17.05 51.785,17.05 52.31,17.575 53.971,17.575 54.096,17.45 55.175,17.45 55.615,17.89 56.675,18.95 56.675,19.286 56.964,19.575 57.541,19.575 58.175,20.209 58.175,21.1 59.98,22.905 59.98,23.15 60.305,23.475 62.025,23.475 62.68,24.13 62.68,26.435 62.175,26.94 62.11,26.94 60.91,28.14 v1(59.98,28.14)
